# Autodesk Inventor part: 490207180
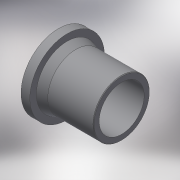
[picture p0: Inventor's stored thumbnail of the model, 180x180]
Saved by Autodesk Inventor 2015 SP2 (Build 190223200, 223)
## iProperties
Created: 2017-07
Part Number: 490207180
Material: Generic
Description: Stub Flange 180
Document SubType Name: Modeling
Designer: Кирилл
Mass: 2125.8 g
Surface Area: 2463.82 cm^2
Volume: 2125.8 cm^3
Density: 1 g/cm^3
Appearance: Default
Author: Кирилл
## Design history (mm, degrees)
derived "490207.ipt"
feature "Solid1::490207.ipt"
tag "TaggingFeature1"
body "Solid1"
other parameters: "d0" = 198, "d1" = 187, "d3" = 144, "d4" = 212, "d17" = 3.6, "d18" = 3.6, "d19" = 3.6, "d21" = 3.6, "d24" = 3.6, "d25" = 3.6, "d26" = 1.8, "d27" = 0, "d32" = 1.8, "L_" = 198, "D_" = 212, "D_1" = 187
